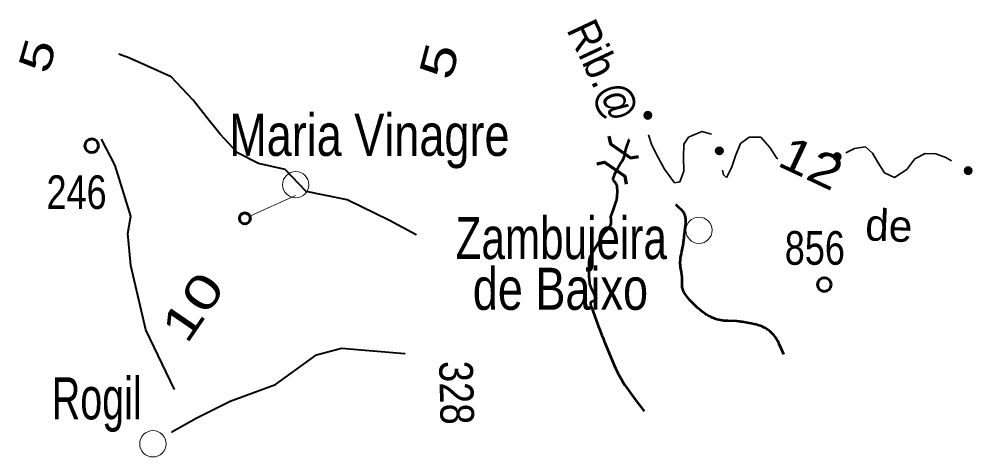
# Model space of a CAD drawing. Extents: x 515932 to 527248, y 4135789 to 4140993.
import ezdxf
from ezdxf.enums import TextEntityAlignment as Align

# ---------------------------------------------------------------- set-up
doc = ezdxf.new("R2010")
doc.units = 0
doc.header["$LTSCALE"] = 160
doc.linetypes.add('SHORT_DASHED', pattern=[2.7, 1.5, -1.2])
for name, color, linetype in [('14', 7, 'Continuous'), ('39', 7, 'Continuous'), ('55', 7, 'Continuous'), ('59', 7, 'Continuous')]:
    doc.layers.add(name, color=color, linetype=linetype)
for name, color, linetype, lineweight in [('16', 7, 'Continuous', 35), ('17', 7, 'Continuous', 13), ('23', 7, 'Continuous', 40), ('27', 7, 'Continuous', 13), ('28', 7, 'Continuous', 70), ('37', 7, 'Continuous', 60), ('53', 7, 'Continuous', 53)]:
    doc.layers.add(name, color=color, linetype=linetype, lineweight=lineweight)

msp = doc.modelspace()

# ---------------------------------------------------------------- hatches: boundary and pattern name
at = {"layer": '16'}
for points in [[(523397.1, 4139804.5, 1), (523400.2, 4139892, 1)], [(524254, 4139382.1, 1), (524243, 4139468.9, 1)], [(525687.2, 4139378.3, 1), (525610, 4139337.2, 1)], [(527242.1, 4139168.6, 1), (527166.7, 4139213, 1)]]:
    msp.add_hatch(color=256, dxfattribs=at).paths.add_polyline_path(points)

# ---------------------------------------------------------------- linework, layer by layer
for points in [[(523407.6, 4139617.7), (523441.2, 4139507), (523497.4, 4139390.5), (523597.4, 4139209), (523717.3, 4139047.5), (523779.4, 4139060.1), (523827.8, 4139185.7), (523823.3, 4139346.3), (523827.8, 4139506.1), (523883, 4139587.7), (524041.9, 4139656.8), (524156.5, 4139625.6)], [(524286, 4139197.5), (524297.5, 4139141.7), (524332, 4139110.3), (524394.2, 4139223.4), (524441.8, 4139368.8), (524497.8, 4139512.3), (524601.4, 4139587.7), (524739.6, 4139587.7), (524850.1, 4139462.1), (524926.1, 4139342.7), (524942.4, 4139331.4)], [(525751.6, 4139402.2), (525851.7, 4139455.8), (525982.9, 4139474.6), (526065.8, 4139399.3), (526132.8, 4139282.9), (526210.9, 4139166.9), (526328.3, 4139110.3), (526473.4, 4139204.5), (526570.1, 4139330.2), (526694.4, 4139393), (526818.1, 4139390.6), (526936.2, 4139349), (527005.2, 4139308.3)]]:
    msp.add_lwpolyline(points, dxfattribs=at)
for centre in [(523398.6, 4139848.2), (524248.5, 4139425.5), (525648.6, 4139357.8), (527204.4, 4139190.8)]:
    msp.add_circle(centre, 43.8, dxfattribs=at)
at = {"layer": '17'}
for centre in [(519217.7, 4139024.2), (524006.5, 4138483), (517521.4, 4135945)]:
    msp.add_circle(centre, 156.2, dxfattribs=at)
at = {"layer": '23'}
for points in [[(520653.5, 4138424.5), (520649.5, 4138426.7), (520332.8, 4138598.9), (519829.1, 4138844.6), (519554.5, 4138900.1), (519343.5, 4138942.9), (519339.7, 4138946.9), (519092.7, 4139204.6), (518776.8, 4139275.9), (518525.4, 4139403.4), (518319.4, 4139624), (518160, 4139826.5), (518000.5, 4140029), (517738.5, 4140304.7), (517459.2, 4140432), (517235.8, 4140531.9), (517115.6, 4140576.6)], [(517777.8, 4136591.5), (517439.2, 4137298.2), (517257.9, 4138062.6), (517225.8, 4138445.7), (517257.8, 4138648.8), (517071.8, 4139252.7), (516911.2, 4139566.7)], [(517743.4, 4136086.1), (517747.4, 4136088.4), (518034.3, 4136249.2), (518440.9, 4136452.7), (518978.5, 4136650.3), (519463.8, 4137003.8), (519760.3, 4137082.2), (520513.2, 4137017.5), (520517.2, 4137017.2)]]:
    msp.add_lwpolyline(points, dxfattribs=at)
at = {"layer": '27'}
msp.add_line((518673.1, 4138650.5), (519216, 4138894.1), dxfattribs=at)
at = {"layer": '27', "lineweight": 60}
msp.add_circle((518613.8, 4138623.9), 65, dxfattribs=at)
at = {"layer": '28'}
for points in [[(522937.6, 4139602.8), (522954.4, 4139510.6), (523194.7, 4139344.2), (523287, 4139360.9)], [(522793.8, 4139273.3), (522886.1, 4139290.1), (523126.4, 4139123.6), (523143.2, 4139031.4)]]:
    msp.add_lwpolyline(points, dxfattribs=at)
at = {"layer": '37'}
for centre in [(516794.7, 4139487.4), (525495.2, 4137837.3)]:
    msp.add_circle(centre, 81.2, dxfattribs=at)
at = {"layer": '53'}
for points in [[(523178.5, 4139558.7), (523173.9, 4139557.6), (523135, 4139441.8), (523131.3, 4139415.2)], [(523015.2, 4139172.7), (522998.7, 4139136.5), (522985.8, 4139105.2), (522984.3, 4139099.2), (522984.1, 4139093.6), (522985, 4139088.3), (522986.6, 4139083.3), (522988.7, 4139078.7), (522994, 4139070), (522999.5, 4139062.4), (523010.2, 4139049.1), (523018.1, 4139039.2), (523023.4, 4139031.7), (523026.7, 4139026), (523028.8, 4139021.8), (523031, 4139015.4), (523031.9, 4139009), (523033, 4138985.9), (523033.7, 4138964.9), (523034.1, 4138946), (523034.1, 4138929.1), (523033, 4138899.4), (523031, 4138877.2), (523028.7, 4138860.7), (523026.4, 4138848.5), (523022.1, 4138830.5), (523016.5, 4138813.1), (522986.1, 4138729.7), (522955.8, 4138642.9), (522955.8, 4138642.9), (522958.6, 4138613.6), (522961.2, 4138587.7), (522961.6, 4138581.8), (522961.5, 4138576.2), (522960.4, 4138565.6), (522958, 4138555.9), (522954.9, 4138547), (522951.2, 4138538.9), (522947.2, 4138531.3), (522938.3, 4138517.5), (522929.4, 4138505.7), (522912.3, 4138485.3), (522885.8, 4138454.9), (522873.7, 4138439.5), (522868.2, 4138431.6), (522863.2, 4138423.7), (522807.8, 4138330.6), (522752.5, 4138237.5), (522724.7, 4138191.4), (522718.4, 4138179.5), (522714, 4138170.3), (522708.3, 4138156.3), (522703.7, 4138141.6), (522701.8, 4138132.5), (522700.6, 4138124.5), (522699.6, 4138110.5), (522699.4, 4138068.4), (522698.8, 4138020.1), (522699.3, 4137971.9), (522700.4, 4137926.7), (522701.1, 4137909.7), (522702.2, 4137894.8), (522705, 4137869), (522708.2, 4137849.9), (522711.4, 4137835.9), (522714.3, 4137825.5), (522719.6, 4137810.2), (522726.1, 4137795.5), (522758.2, 4137730), (522787.2, 4137662.4), (522787.2, 4137662.4), (522757.4, 4137646.7), (522730.5, 4137633), (522727.7, 4137631.4), (522723.3, 4137627.6), (522720.4, 4137623.4), (522718.6, 4137618.9), (522717.7, 4137614.2), (522717.4, 4137609.5), (522717.6, 4137604.8), (522719, 4137595.5), (522721.3, 4137586.9), (522723.8, 4137579.2), (522729.2, 4137565.4), (522737.9, 4137545.1), (522741.9, 4137535.7), (522745.3, 4137526.9), (522810.6, 4137345.7), (522827.5, 4137300.6), (522853.9, 4137233.1), (522867.7, 4137199.5), (522881.9, 4137166.1), (523001.2, 4136878.7), (523017, 4136843.4), (523031.3, 4136812.7), (523044.2, 4136786.1), (523055.9, 4136763.1), (523077.2, 4136723.3), (523094, 4136693.9), (523107.1, 4136672.2), (523127.7, 4136640.2)], [(523830, 4138685), (523825.6, 4138692.4), (523818, 4138703), (523809.3, 4138712.9), (523768.7, 4138754.4), (523734.7, 4138783.4), (523730.7, 4138786.8)], [(525016.2, 4137005.8), (524986.2, 4137071.2), (524960.8, 4137130.7), (524953.9, 4137146), (524946.8, 4137160.1), (524939.7, 4137173.1), (524932.6, 4137185.1), (524925.5, 4137196.2), (524911.3, 4137216.2), (524897.8, 4137233.1), (524885.2, 4137247.3), (524873.6, 4137259.2), (524863.1, 4137269.3), (524853.5, 4137277.7), (524835.9, 4137291.8), (524822.2, 4137301.7), (524811.6, 4137308.8), (524795.1, 4137318.7), (524778, 4137327.8), (524762.2, 4137335.2), (524747.3, 4137341.6), (524733.4, 4137347.1), (524707, 4137356), (524683.9, 4137362.7), (524663.5, 4137367.8), (524627.8, 4137375.5), (524600.8, 4137380.4), (524519.4, 4137393.6), (524502.1, 4137396.1), (524485.8, 4137398), (524455.2, 4137400.5), (524347.6, 4137404.7), (524320.7, 4137406.4), (524300.6, 4137408.2), (524285.5, 4137410.1), (524263, 4137413.6), (524240.6, 4137418.3), (524219.5, 4137423.9), (524200.2, 4137430), (524182.6, 4137436.4), (524166.3, 4137443.1), (524151.4, 4137449.8), (524137.5, 4137456.6), (524124.8, 4137463.3), (524101.3, 4137476.9), (524081.2, 4137489.9), (524063.8, 4137501.9), (524048.9, 4137513), (524023, 4137533.5), (524003.9, 4137549.8), (523989.7, 4137562.6), (523968.4, 4137582.4), (523947.3, 4137603.1), (523921.2, 4137629.3), (523898.9, 4137652.6), (523880.3, 4137673.2), (523865, 4137691.5), (523852.6, 4137707.9), (523842.7, 4137722.5), (523834.7, 4137735.4), (523828.4, 4137747), (523823.5, 4137757.2), (523819.6, 4137766.3), (523813.8, 4137782.6), (523810.5, 4137795), (523808.5, 4137804.5), (523806.6, 4137819), (523805.9, 4137833.8), (523805.7, 4137875.4), (523806.9, 4137920.3), (523806.9, 4137920.3), (523798.6, 4137984.3), (523788.9, 4138044.8), (523786.2, 4138066.8), (523785, 4138087.4), (523785, 4138106.7), (523785.8, 4138124.9), (523787.2, 4138141.9), (523789, 4138157.9), (523793.5, 4138187.9), (523798.3, 4138214.1), (523817.2, 4138306.1), (523821.5, 4138329), (523824.3, 4138346.2), (523827.7, 4138372.1), (523830, 4138397.9), (523831.6, 4138417.8), (523833.8, 4138437), (523838.9, 4138474.1), (523843.5, 4138507.1), (523847.1, 4138536.1), (523849.3, 4138561.2), (523850.3, 4138582.9), (523850.2, 4138601.4), (523849.2, 4138617.3), (523847.5, 4138630.8), (523845.4, 4138642.4), (523843, 4138652.2), (523840.5, 4138660.6), (523835, 4138674.8), (523830, 4138685)], [(523127.7, 4136640.2), (523149.5, 4136608.9), (523249.3, 4136471.3), (523355, 4136332.6)]]:
    msp.add_lwpolyline(points, dxfattribs=at)
at = {"layer": '53', "linetype": 'SHORT_DASHED'}
msp.add_lwpolyline([(523015.2, 4139172.7), (523074, 4139279.6), (523098.3, 4139308.3), (523116.1, 4139342.1), (523129.9, 4139386.2), (523131.3, 4139415.2)], dxfattribs=at)

# ---------------------------------------------------------------- texts
at = {"layer": '14'}
for s, width, p in [('Maria Vinagre', 0.8, (518427.2, 4139366.4)), ('Zambujeira', 0.75, (521116.9, 4138140.6)), ('de Baixo', 0.8, (521320.6, 4137537.4)), ('Rogil', 0.7, (516321.1, 4136235.3))]:
    msp.add_text(s, height=500, dxfattribs=dict(at, width=width)).set_placement(p)
at = {"layer": '27'}
for s, rotation, width, p in [('5', 75.348, 1.35, (521113.8, 4140443.4)), ('12', 334.884, 1.25, (525254.6, 4139100.3)), ('10', 55.551, 1.4, (518159, 4137460.5))]:
    msp.add_text(s, height=400, rotation=rotation, dxfattribs=dict(at, width=width)).set_placement(p, align=Align.CENTER)
at = {"layer": '37', "width": 0.8}
for s, p in [('246', (516614.9, 4138735.4)), ('856', (525382.2, 4138072.9))]:
    msp.add_text(s, height=400, dxfattribs=at).set_placement(p, align=Align.CENTER)
at = {"layer": '39', "width": 0.85}
msp.add_text('328', height=400, rotation=271.34, dxfattribs=at).set_placement((520929, 4136547.3), align=Align.CENTER)
at = {"layer": '55', "width": 1.35}
msp.add_text('5', height=375, rotation=73.977, dxfattribs=at).set_placement((516277.1, 4140326.5))
at = {"layer": '59', "width": 0.9}
msp.add_text('Rib.@', height=375, rotation=295.181, dxfattribs=at).set_placement((522429.1, 4140866.6))
at = {"layer": '59'}
msp.add_text('de', height=375, rotation=357.606, dxfattribs=at).set_placement((525975.5, 4138363.9))

doc.saveas('drawing.dxf')
